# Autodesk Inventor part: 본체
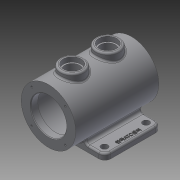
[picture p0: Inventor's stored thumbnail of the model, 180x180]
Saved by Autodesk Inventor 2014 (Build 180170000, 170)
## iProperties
Created: 2014-12
Part Number: 본체
Material: 일반
Document SubType Name: Modeling
Designer: Owner
Density: 1 g/cm^3
Appearance: 기본값
Author: Owner
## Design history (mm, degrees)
sketch "스케치1"
  geometry: C1 r 46 at (0, 0); 1 further point
  constraints: 1 centre point, 1 coincident
  dimensions: "d0" = 92 diameter of C1
extrude "돌출1" new body sketch "스케치1" stored distance "d1" = 140; taper "d2" = 0 deg
hole "구멍1" diameter "d5" = 60; stored, may be unused: countersink angle "d9" = 90 deg, drill point angle "d11" = 0 deg; dims "d3" = 10, "d4" = 10, "d6" = 6, "d7" = 4, "d8" = 2, "d10" = 12
hole "구멍2" diameter "d14" = 75; stored, may be unused: countersink angle "d18" = 90 deg, drill point angle "d20" = 0 deg; dims "d12" = 10, "d13" = 10, "d15" = 6, "d16" = 4, "d17" = 2, "d19" = 116
hole "구멍3" diameter "d23" = 60; stored, may be unused: countersink angle "d27" = 90 deg, drill point angle "d29" = 0 deg; dims "d21" = 10, "d22" = 10, "d24" = 6, "d25" = 4, "d26" = 2, "d28" = 12
node "작업 평면1"
sketch "스케치2"
  geometry: L1 (-65, -40)-(65, -40); L2 (65, -40)-(65, 55); L3 (65, 55)-(-65, 55); L4 (-65, 55)-(-65, -40); L5 (46, 70)-(-46, 70) reference; 2 further points
  constraints: 8 end point, 2 parallel, 1 horizontal, 1 midpoint, 1 perpendicular, 1 vertical alignment
  dimensions: "d31" = 95 distance of L1.end L2.end; "d32" = 130 distance of L2.end L3.end; "d33" = 15 distance between parallel lines of L3 L5
extrude "돌출2" join sketch "스케치2" distance "d34" = 10; taper "d35" = 0 deg
fillet "모깎기1" dims "d36" = 10
node "작업 평면2"
sketch "스케치3"
  geometry: L1 (-46, -70)-(46, -70) reference; L2 (46, 70)-(-46, 70) reference; C1 r 20 at (0, -30); C2 r 20 at (0, 30); 1 further point
  constraints: 2 centre point, 2 vertical alignment, 1 equal radius
  dimensions: "d38" = 40 diameter of C1; "d39" = 40 distance from line of L1 C1.centre; "d40" = 40 distance from line of L2 C2.centre
extrude "돌출3" join sketch "스케치3" stored distance "d41" = 10; taper "d42" = 0 deg
hole "구멍4" diameter "d45" = 25; stored, may be unused: countersink angle "d49" = 90 deg, drill point angle "d51" = 0 deg; dims "d43" = 10, "d44" = 10, "d46" = 6, "d47" = 30, "d48" = 8, "d50" = 12
hole "구멍5" diameter "d54" = 25; stored, may be unused: countersink angle "d58" = 90 deg, drill point angle "d60" = 0 deg; dims "d52" = 10, "d53" = 10, "d55" = 6, "d56" = 30, "d57" = 8, "d59" = 12
sketch "스케치4"
  geometry: L1 (55, 55)-(22.716, 55) reference; L2 (65, -30)-(65, 45) reference; 2 further points
  dimensions: "d61" = 12.5 distance from line of L1 point (52, 42.5); "d62" = 13 distance from line of L2 point (52, 42.5)
hole "구멍6" sketch "스케치4" at (52, 42.5) diameter "d63" = 11; stored, may be unused: countersink angle "d67" = 90 deg, drill point angle "d69" = 0 deg; dims "d64" = 6, "d65" = 30, "d66" = 8, "d68" = 12
sketch "스케치5"
  geometry: L1 (22.716, -40)-(55, -40) reference; L2 (65, -30)-(65, 45) reference; 2 further points
  dimensions: "d70" = 12.5 distance from line of L1 point (52, -27.5); "d71" = 13 distance from line of L2 point (52, -27.5)
hole "구멍7" sketch "스케치5" at (52, -27.5) diameter "d72" = 11; stored, may be unused: countersink angle "d76" = 90 deg, drill point angle "d78" = 0 deg; dims "d73" = 6, "d74" = 30, "d75" = 8, "d77" = 12
fillet "모깎기2" dims "d79" = 3
fillet "모깎기3" dims "d80" = 3
chamfer "모따기1" distance "d81" = 1; stored, may be unused: second distance "d82" = 2, angle "d83" = 45 deg
sketch "스케치6"
  geometry: L1 (0, 0)-(28.284, 28.284); L2 (0, 0)-(40, 0); C1 r 31 at (0, 0) reference; 1 further point
  constraints: 4 end point, 1 coincident, 1 equal length, 1 horizontal
  dimensions: "d84" = 40 distance of L1.start L1.end; "d85" = 45 deg angle of L2 L1
hole "구멍8" sketch "스케치6" at (28.284, 28.284) diameter "d86" = 3.242; stored, may be unused: countersink angle "d90" = 90 deg, drill point angle "d92" = 118 deg; dims "d87" = 8, "d88" = 30, "d89" = 8, "d91" = 10
fillet "모깎기4" dims "d96" = 5
fillet "모깎기5" dims "d97" = 3
sketch "스케치7" dims "d54" = 25, "d56" = 30, "d57" = 8, "d59" = 12
  geometry: L1 (65, -30)-(65, 45) reference; C1 r 5.5 at (52, -27.5) reference; 2 further points
  constraints: 1 other
  dimensions: "d98" = 35 vertical distance of C1.centre point (57, 7.5); "d99" = 8 distance from line of L1 point (57, 7.5)
feature "엠보싱1" sketch "스케치7" dims "d100" = 1, "d101" = 0
node "솔리드1"
mirror "대칭1"
pattern_circular "원형 패턴1" dims angle "d94" = 360 deg
mirror "대칭2"
other parameters: "d37" = 56
